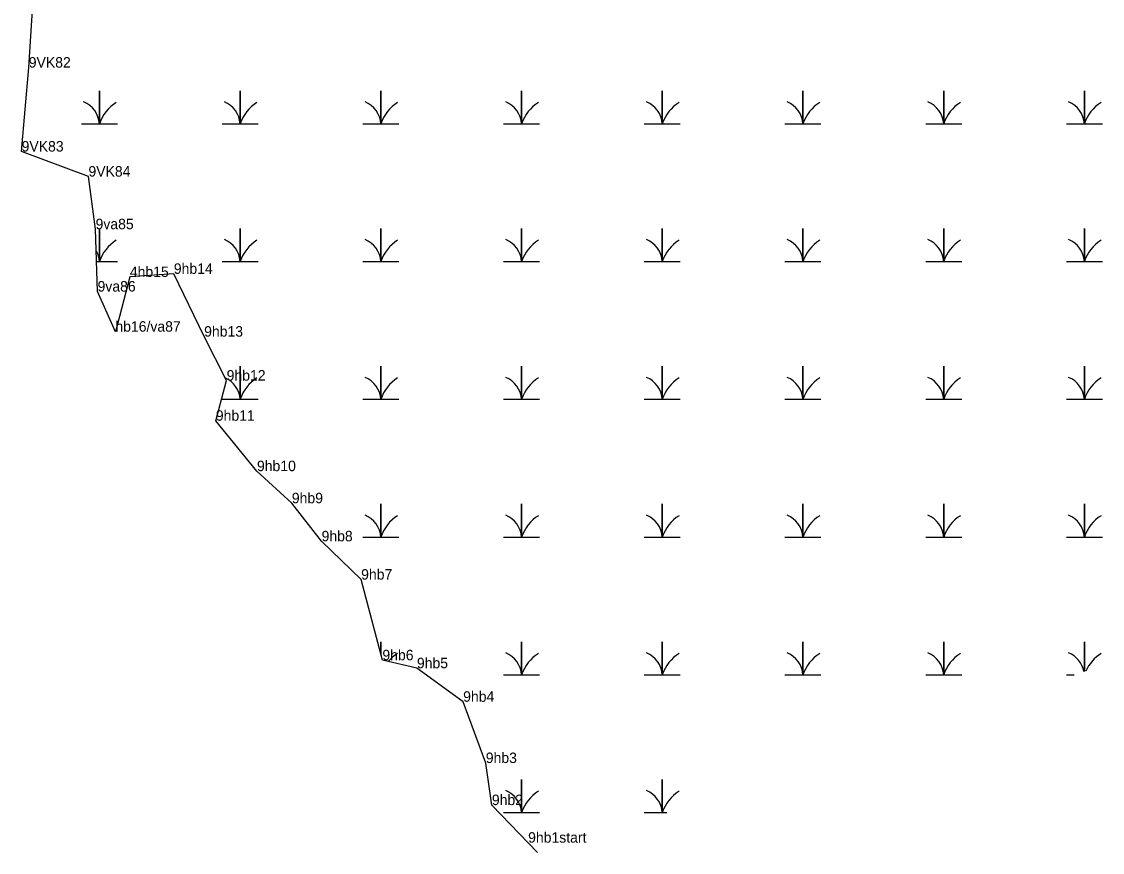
# Model space of a CAD drawing. Extents: x 2072529 to 2268796, y 436423 to 470406.
# Drawn here: x 2205507 to 2206024, y 446974 to 447371 of the extents above; entities that cross this region are included whole.
import ezdxf

# ---------------------------------------------------------------- set-up
doc = ezdxf.new("R2010")
doc.units = 0
for name, color, linetype in [('Exist Environmental Wetland Boundary', 7, 'Continuous'), ('Exist Environmental Wetland Boundary Cogo Comment', 7, 'Continuous'), ('Exist Hydro Swamp or Marsh', 7, 'Continuous'), ('Old_Level_20', 7, 'Continuous')]:
    doc.layers.add(name, color=color, linetype=linetype)

msp = doc.modelspace()

# ---------------------------------------------------------------- linework, layer by layer
at = {"layer": 'Exist Environmental Wetland Boundary'}
for points in [[(2205552.17, 447223.17), (2205543.65, 447242.35), (2205542.7, 447272.12), (2205539.3, 447297.26), (2205507.35, 447309.23), (2205510.77, 447349.31), (2205512.65, 447379.36)], [(2205753.91, 446974.47), (2205732.12, 446997.05), (2205729.21, 447017.14), (2205718.39, 447046.41), (2205696.29, 447062.42), (2205679.8, 447066.23), (2205669.63, 447104.75), (2205650.73, 447123.04), (2205636.51, 447141.22), (2205619.85, 447156.56), (2205600.18, 447180.63), (2205605.35, 447199.81), (2205594.59, 447220.82), (2205580.1, 447250.8), (2205559.08, 447249.3), (2205552.17, 447223.17)]]:
    msp.add_lwpolyline(points, dxfattribs=at)
at = {"layer": 'Exist Hydro Swamp or Marsh'}
for points in [[(2205535.97, 447322.48), (2205544.57, 447322.48), (2205544.57, 447338.27), (2205544.57, 447322.48), (2205553.17, 447322.48)], [(2205603.22, 447322.48), (2205611.82, 447322.48), (2205611.82, 447338.27), (2205611.82, 447322.48), (2205620.42, 447322.48)], [(2205670.47, 447322.48), (2205679.07, 447322.48), (2205679.07, 447338.27), (2205679.07, 447322.48), (2205687.67, 447322.48)], [(2205737.72, 447322.48), (2205746.32, 447322.48), (2205746.32, 447338.27), (2205746.32, 447322.48), (2205754.92, 447322.48)], [(2205804.97, 447322.48), (2205813.57, 447322.48), (2205813.57, 447338.27), (2205813.57, 447322.48), (2205822.17, 447322.48)], [(2205872.22, 447322.48), (2205880.82, 447322.48), (2205880.82, 447338.27), (2205880.82, 447322.48), (2205889.42, 447322.48)], [(2205939.47, 447322.48), (2205948.07, 447322.48), (2205948.07, 447338.27), (2205948.07, 447322.48), (2205956.67, 447322.48)], [(2206006.72, 447322.48), (2206015.32, 447322.48), (2206015.32, 447338.27), (2206015.32, 447322.48), (2206023.92, 447322.48)], [(2205543.19, 447256.68), (2205544.57, 447256.68), (2205544.57, 447272.47), (2205544.57, 447256.68), (2205553.17, 447256.68)], [(2205603.22, 447256.68), (2205611.82, 447256.68), (2205611.82, 447272.47), (2205611.82, 447256.68), (2205620.42, 447256.68)], [(2205670.47, 447256.68), (2205679.07, 447256.68), (2205679.07, 447272.47), (2205679.07, 447256.68), (2205687.67, 447256.68)], [(2205737.72, 447256.68), (2205746.32, 447256.68), (2205746.32, 447272.47), (2205746.32, 447256.68), (2205754.92, 447256.68)], [(2205804.97, 447256.68), (2205813.57, 447256.68), (2205813.57, 447272.47), (2205813.57, 447256.68), (2205822.17, 447256.68)], [(2205872.22, 447256.68), (2205880.82, 447256.68), (2205880.82, 447272.47), (2205880.82, 447256.68), (2205889.42, 447256.68)], [(2205939.47, 447256.68), (2205948.07, 447256.68), (2205948.07, 447272.47), (2205948.07, 447256.68), (2205956.67, 447256.68)], [(2206006.72, 447256.68), (2206015.32, 447256.68), (2206015.32, 447272.47), (2206015.32, 447256.68), (2206023.92, 447256.68)], [(2205603.22, 447190.88), (2205611.82, 447190.88), (2205611.82, 447206.67), (2205611.82, 447190.88), (2205620.42, 447190.88)], [(2205670.47, 447190.88), (2205679.07, 447190.88), (2205679.07, 447206.67), (2205679.07, 447190.88), (2205687.67, 447190.88)], [(2205737.72, 447190.88), (2205746.32, 447190.88), (2205746.32, 447206.67), (2205746.32, 447190.88), (2205754.92, 447190.88)], [(2205804.97, 447190.88), (2205813.57, 447190.88), (2205813.57, 447206.67), (2205813.57, 447190.88), (2205822.17, 447190.88)], [(2205872.22, 447190.88), (2205880.82, 447190.88), (2205880.82, 447206.67), (2205880.82, 447190.88), (2205889.42, 447190.88)], [(2205939.47, 447190.88), (2205948.07, 447190.88), (2205948.07, 447206.67), (2205948.07, 447190.88), (2205956.67, 447190.88)], [(2206006.72, 447190.88), (2206015.32, 447190.88), (2206015.32, 447206.67), (2206015.32, 447190.88), (2206023.92, 447190.88)], [(2205670.47, 447125.08), (2205679.07, 447125.08), (2205679.07, 447140.87), (2205679.07, 447125.08), (2205687.67, 447125.08)], [(2205737.72, 447125.08), (2205746.32, 447125.08), (2205746.32, 447140.87), (2205746.32, 447125.08), (2205754.92, 447125.08)], [(2205804.97, 447125.08), (2205813.57, 447125.08), (2205813.57, 447140.87), (2205813.57, 447125.08), (2205822.17, 447125.08)], [(2205872.22, 447125.08), (2205880.82, 447125.08), (2205880.82, 447140.87), (2205880.82, 447125.08), (2205889.42, 447125.08)], [(2205939.47, 447125.08), (2205948.07, 447125.08), (2205948.07, 447140.87), (2205948.07, 447125.08), (2205956.67, 447125.08)], [(2206006.72, 447125.08), (2206015.32, 447125.08), (2206015.32, 447140.87), (2206015.32, 447125.08), (2206023.92, 447125.08)], [(2205679.07, 447069), (2205679.07, 447075.07), (2205679.07, 447069)], [(2205737.72, 447059.28), (2205746.32, 447059.28), (2205746.32, 447075.07), (2205746.32, 447059.28), (2205754.92, 447059.28)], [(2205804.97, 447059.28), (2205813.57, 447059.28), (2205813.57, 447075.07), (2205813.57, 447059.28), (2205822.17, 447059.28)], [(2205872.22, 447059.28), (2205880.82, 447059.28), (2205880.82, 447075.07), (2205880.82, 447059.28), (2205889.42, 447059.28)], [(2205939.47, 447059.28), (2205948.07, 447059.28), (2205948.07, 447075.07), (2205948.07, 447059.28), (2205956.67, 447059.28)], [(2206015.32, 447060.85), (2206015.32, 447075.07), (2206015.32, 447060.85)], [(2206006.72, 447059.28), (2206010.36, 447059.28)], [(2205737.72, 446993.48), (2205746.32, 446993.48), (2205746.32, 447009.27), (2205746.32, 446993.48), (2205754.92, 446993.48)], [(2205804.97, 446993.48), (2205813.57, 446993.48), (2205813.57, 447009.27), (2205813.57, 446993.48), (2205815.68, 446993.48)]]:
    msp.add_lwpolyline(points, dxfattribs=at)
for centre, radius, start, end in [((2205532.3, 447321.6), 12.3, 4.1403, 67.535), ((2205562.81, 447316.42), 19.22, 122.1274, 161.6222), ((2205599.55, 447321.6), 12.3, 4.1403, 67.535), ((2205630.06, 447316.42), 19.22, 122.1274, 161.6222), ((2205666.8, 447321.6), 12.3, 4.1403, 67.535), ((2205697.31, 447316.42), 19.22, 122.1274, 161.6222), ((2205734.05, 447321.6), 12.3, 4.1403, 67.535), ((2205764.56, 447316.42), 19.22, 122.1274, 161.6222), ((2205801.3, 447321.6), 12.3, 4.1403, 67.535), ((2205831.81, 447316.42), 19.22, 122.1274, 161.6222), ((2205868.55, 447321.6), 12.3, 4.1403, 67.535), ((2205899.06, 447316.42), 19.22, 122.1274, 161.6222), ((2205935.8, 447321.6), 12.3, 4.1403, 67.535), ((2205966.31, 447316.42), 19.22, 122.1274, 161.6222), ((2206003.05, 447321.6), 12.3, 4.1403, 67.535), ((2206033.56, 447316.42), 19.22, 122.1274, 161.6222), ((2205562.81, 447250.62), 19.22, 122.1274, 161.6222), ((2205599.55, 447255.8), 12.3, 4.1403, 67.535), ((2205630.06, 447250.62), 19.22, 122.1274, 161.6222), ((2205666.8, 447255.8), 12.3, 4.1403, 67.535), ((2205697.31, 447250.62), 19.22, 122.1274, 161.6222), ((2205734.05, 447255.8), 12.3, 4.1403, 67.535), ((2205764.56, 447250.62), 19.22, 122.1274, 161.6222), ((2205801.3, 447255.8), 12.3, 4.1403, 67.535), ((2205831.81, 447250.62), 19.22, 122.1274, 161.6222), ((2205868.55, 447255.8), 12.3, 4.1403, 67.535), ((2205899.06, 447250.62), 19.22, 122.1274, 161.6222), ((2205935.8, 447255.8), 12.3, 4.1403, 67.535), ((2205966.31, 447250.62), 19.22, 122.1274, 161.6222), ((2206003.05, 447255.8), 12.3, 4.1403, 67.535), ((2206033.56, 447250.62), 19.22, 122.1274, 161.6222), ((2205532.3, 447255.8), 12.3, 4.1403, 29.2758), ((2205599.55, 447190), 12.3, 4.1403, 65.5524), ((2205630.06, 447184.82), 19.22, 122.1274, 161.6222), ((2205666.8, 447190), 12.3, 4.1403, 67.535), ((2205697.31, 447184.82), 19.22, 122.1274, 161.6222), ((2205734.05, 447190), 12.3, 4.1403, 67.535), ((2205764.56, 447184.82), 19.22, 122.1274, 161.6222), ((2205801.3, 447190), 12.3, 4.1403, 67.535), ((2205831.81, 447184.82), 19.22, 122.1274, 161.6222), ((2205868.55, 447190), 12.3, 4.1403, 67.535), ((2205899.06, 447184.82), 19.22, 122.1274, 161.6222), ((2205935.8, 447190), 12.3, 4.1403, 67.535), ((2205966.31, 447184.82), 19.22, 122.1274, 161.6222), ((2206003.05, 447190), 12.3, 4.1403, 67.535), ((2206033.56, 447184.82), 19.22, 122.1274, 161.6222), ((2205666.8, 447124.2), 12.3, 4.1403, 67.535), ((2205697.31, 447119.02), 19.22, 122.1274, 161.6222), ((2205734.05, 447124.2), 12.3, 4.1403, 67.535), ((2205764.56, 447119.02), 19.22, 122.1274, 161.6222), ((2205801.3, 447124.2), 12.3, 4.1403, 67.535), ((2205831.81, 447119.02), 19.22, 122.1274, 161.6222), ((2205868.55, 447124.2), 12.3, 4.1403, 67.535), ((2205899.06, 447119.02), 19.22, 122.1274, 161.6222), ((2205935.8, 447124.2), 12.3, 4.1403, 67.535), ((2205966.31, 447119.02), 19.22, 122.1274, 161.6222), ((2206003.05, 447124.2), 12.3, 4.1403, 67.535), ((2206033.56, 447119.02), 19.22, 122.1274, 161.6222), ((2205697.31, 447053.22), 19.22, 122.1274, 139.9771), ((2205734.05, 447058.4), 12.3, 4.1403, 67.535), ((2205764.56, 447053.22), 19.22, 122.1274, 161.6222), ((2205801.3, 447058.4), 12.3, 4.1403, 67.535), ((2205831.81, 447053.22), 19.22, 122.1274, 161.6222), ((2205868.55, 447058.4), 12.3, 4.1403, 67.535), ((2205899.06, 447053.22), 19.22, 122.1274, 161.6222), ((2205935.8, 447058.4), 12.3, 4.1403, 67.535), ((2205966.31, 447053.22), 19.22, 122.1274, 161.6222), ((2206003.05, 447058.4), 12.3, 11.2135, 67.535), ((2206033.56, 447053.22), 19.22, 122.1274, 155.9041), ((2205734.05, 446992.6), 12.3, 4.1403, 67.535), ((2205764.56, 446987.42), 19.22, 122.1274, 161.6222), ((2205801.3, 446992.6), 12.3, 4.1403, 67.535), ((2205831.81, 446987.42), 19.22, 122.1274, 161.6222)]:
    msp.add_arc(centre, radius, start, end, dxfattribs=at)
at = {"layer": 'Old_Level_20'}
for p, q in [((2205510.77, 447349.31), (2205510.77, 447349.31)), ((2205507.35, 447309.23), (2205507.35, 447309.23)), ((2205539.3, 447297.26), (2205539.3, 447297.26)), ((2205542.7, 447272.12), (2205542.7, 447272.12)), ((2205542.7, 447272.12), (2205542.7, 447272.12)), ((2205559.08, 447249.3), (2205559.08, 447249.3)), ((2205559.08, 447249.3), (2205559.08, 447249.3)), ((2205580.1, 447250.8), (2205580.1, 447250.8)), ((2205580.1, 447250.8), (2205580.1, 447250.8)), ((2205543.65, 447242.35), (2205543.65, 447242.35)), ((2205543.65, 447242.35), (2205543.65, 447242.35)), ((2205552.17, 447223.17), (2205552.17, 447223.17)), ((2205552.17, 447223.17), (2205552.17, 447223.17)), ((2205594.59, 447220.82), (2205594.59, 447220.82)), ((2205594.59, 447220.82), (2205594.59, 447220.82)), ((2205605.35, 447199.81), (2205605.35, 447199.81)), ((2205605.35, 447199.81), (2205605.35, 447199.81)), ((2205600.18, 447180.63), (2205600.18, 447180.63)), ((2205600.18, 447180.63), (2205600.18, 447180.63)), ((2205619.85, 447156.56), (2205619.85, 447156.56)), ((2205619.85, 447156.56), (2205619.85, 447156.56)), ((2205636.51, 447141.22), (2205636.51, 447141.22)), ((2205636.51, 447141.22), (2205636.51, 447141.22)), ((2205650.73, 447123.04), (2205650.73, 447123.04)), ((2205650.73, 447123.04), (2205650.73, 447123.04)), ((2205669.63, 447104.75), (2205669.63, 447104.75)), ((2205669.63, 447104.75), (2205669.63, 447104.75)), ((2205679.8, 447066.23), (2205679.8, 447066.23)), ((2205679.8, 447066.23), (2205679.8, 447066.23)), ((2205696.29, 447062.42), (2205696.29, 447062.42)), ((2205696.29, 447062.42), (2205696.29, 447062.42)), ((2205718.39, 447046.41), (2205718.39, 447046.41)), ((2205718.39, 447046.41), (2205718.39, 447046.41)), ((2205729.21, 447017.14), (2205729.21, 447017.14)), ((2205729.21, 447017.14), (2205729.21, 447017.14)), ((2205732.12, 446997.05), (2205732.12, 446997.05)), ((2205732.12, 446997.05), (2205732.12, 446997.05)), ((2205749.44, 446979.1), (2205749.44, 446979.1)), ((2205749.44, 446979.1), (2205749.44, 446979.1))]:
    msp.add_line(p, q, dxfattribs=at)

# ---------------------------------------------------------------- texts
at = {"layer": 'Exist Environmental Wetland Boundary Cogo Comment'}
for s, p in [('9VK82', (2205510.77, 447349.31)), ('9VK83', (2205507.35, 447309.23)), ('9VK84', (2205539.3, 447297.26)), ('9va85', (2205542.7, 447272.12)), ('4hb15', (2205559.08, 447249.3)), ('9hb14', (2205580.1, 447250.8)), ('9va86', (2205543.65, 447242.35)), ('hb16/va87', (2205552.17, 447223.17)), ('9hb13', (2205594.59, 447220.82)), ('9hb12', (2205605.35, 447199.81)), ('9hb11', (2205600.18, 447180.63)), ('9hb10', (2205619.85, 447156.56)), ('9hb9', (2205636.51, 447141.22)), ('9hb8', (2205650.73, 447123.04)), ('9hb7', (2205669.63, 447104.75)), ('9hb6', (2205679.8, 447066.23)), ('9hb5', (2205696.29, 447062.42)), ('9hb4', (2205718.39, 447046.41)), ('9hb3', (2205729.21, 447017.14)), ('9hb2', (2205732.12, 446997.05)), ('9hb1start', (2205749.44, 446979.1))]:
    msp.add_text(s, height=5, dxfattribs=at).set_placement(p)

doc.saveas('drawing.dxf')
